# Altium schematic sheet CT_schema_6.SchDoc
size 352 x 211 mm
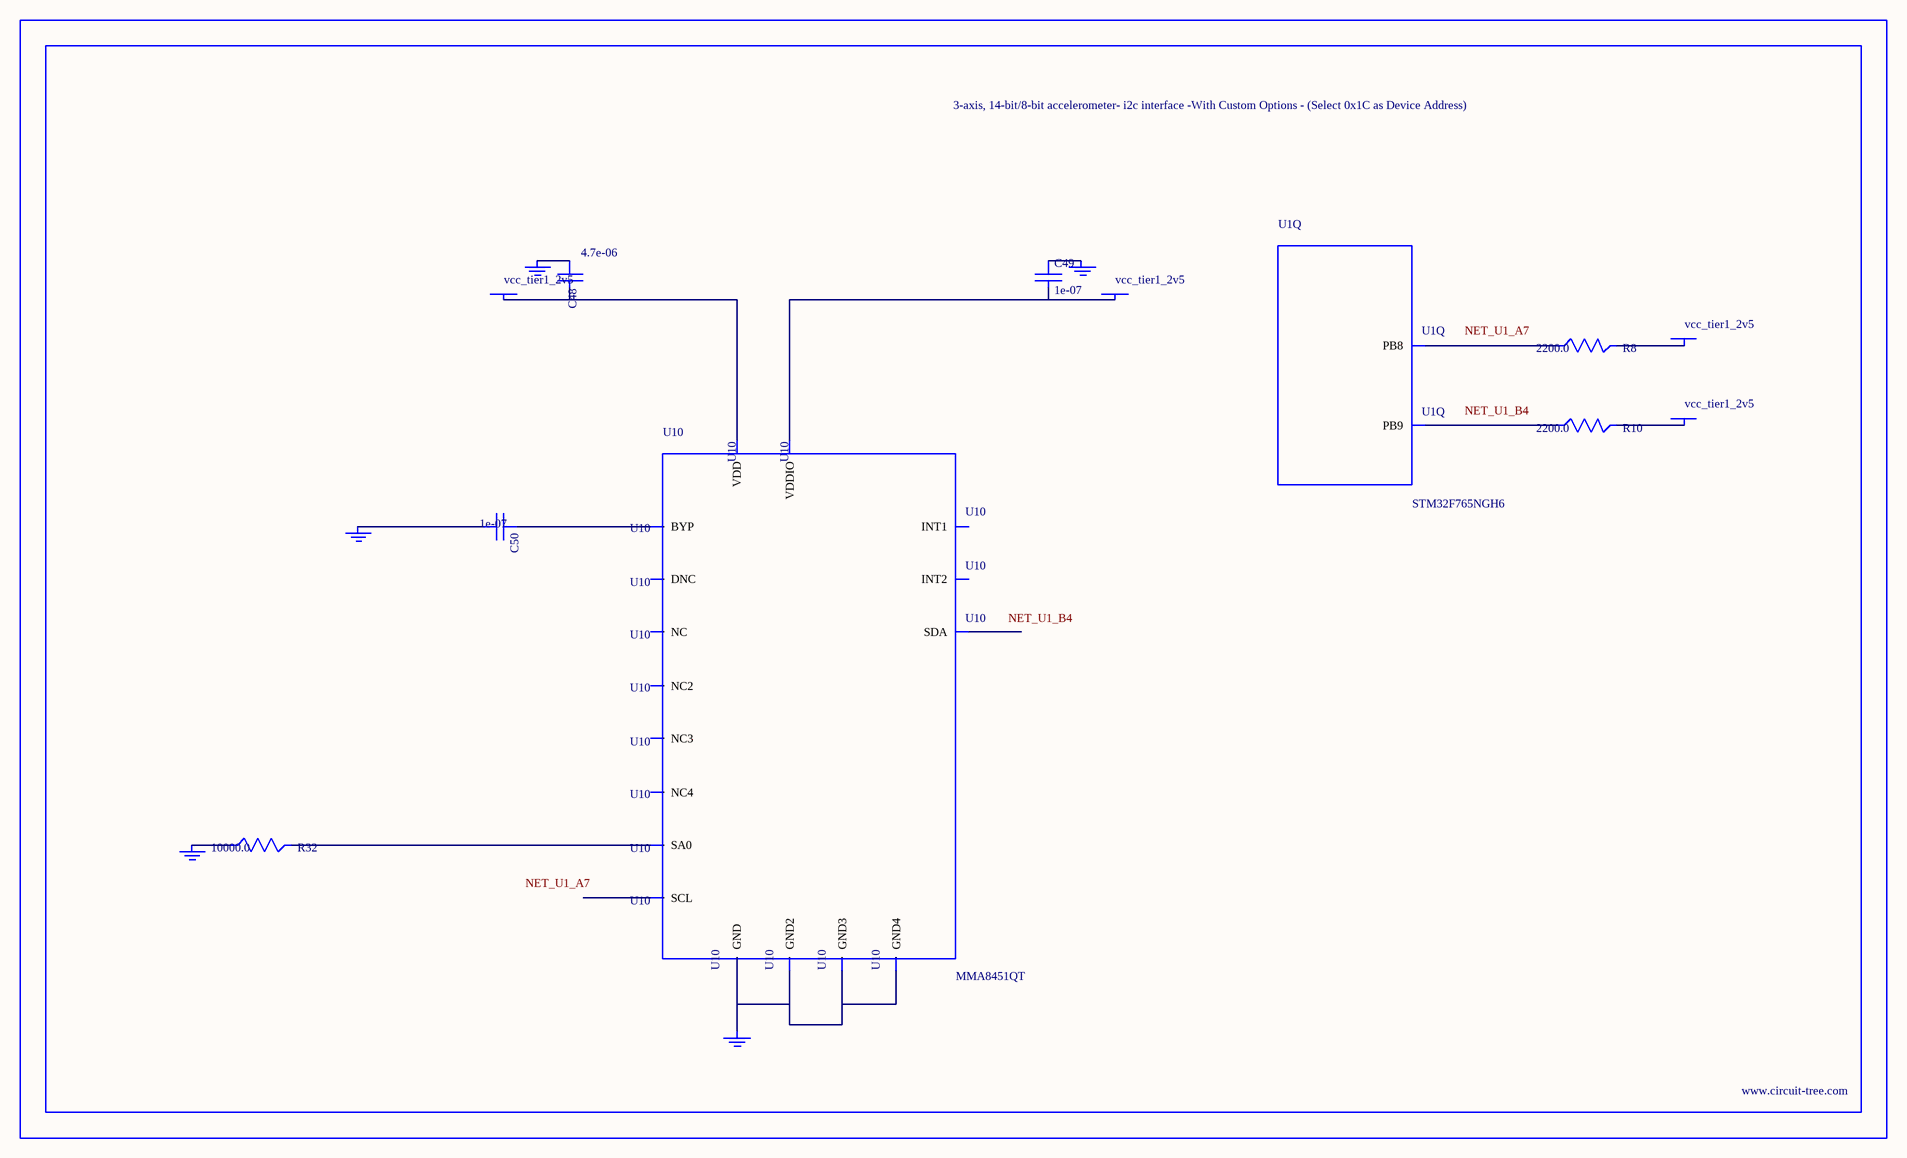
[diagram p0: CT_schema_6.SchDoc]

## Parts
BORDER5  (no value)
C48  4.7e-06  [C0805]
C49  1e-07  [C0402]
C50  1e-07  [C0402]
GND_INSTANCE_5_0  (no value)
GND_INSTANCE_5_1  (no value)
GND_INSTANCE_5_2  (no value)
GND_INSTANCE_5_3  (no value)
GND_INSTANCE_5_4  (no value)
POWER_INSTANCE_5_0  vcc_tier1_2v5
POWER_INSTANCE_5_1  vcc_tier1_2v5
POWER_INSTANCE_5_2  vcc_tier1_2v5
POWER_INSTANCE_5_3  vcc_tier1_2v5
R8  2200.0  [R0603]
R10  2200.0  [R0603]
R32  10000.0  [R0603]
U1  STM32F765NGH6  [TFBGA216]  (part Q of 18)
U10  MMA8451QT  [QFN-16]

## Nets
NetC48_1: C48.1 GND_INSTANCE_5_3.0(GND)
NetC48_2: C48.2 POWER_INSTANCE_5_1.0(PWR) U10.14(VDD)
NetC49_1: C49.1 GND_INSTANCE_5_0.0(GND)
NetC49_2: C49.2 POWER_INSTANCE_5_0.0(PWR) U10.1(VDDIO)
NetC50_1: C50.1 U10.2(BYP)
NetC50_2: C50.2 GND_INSTANCE_5_1.0(GND)
NetGND_INSTANCE_5_2_0: GND_INSTANCE_5_2.0(GND) R32.1
NetGND_INSTANCE_5_4_0: GND_INSTANCE_5_4.0(GND) U10.5(GND) U10.10(GND2) U10.12(GND3) U10.17(GND4)
NetPOWER_INSTANCE_5_2_0: POWER_INSTANCE_5_2.0(PWR) R8.2
NetPOWER_INSTANCE_5_3_0: POWER_INSTANCE_5_3.0(PWR) R10.2
NetR8_1: R8.1 U1.A7(PB8)
NetR10_1: R10.1 U1.B4(PB9)
NetR32_2: R32.2 U10.7(SA0)

Not connected (* = marked no-connect by the designer): U10 3(DNC) 4(SCL) 6(SDA) 8(NC) 9(INT2) 11(INT1) 13(NC2) 15(NC3) 16(NC4)

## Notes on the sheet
- Labels drawn without touching a wire or pin: NET_U1_A7, NET_U1_B4

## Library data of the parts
BORDER5 = BORDER_PAGE5
C48 = C0805C475K4RACTU
C49 C50 = C0402C104K3RACTU
GND_INSTANCE_5_0-GND_INSTANCE_5_4 = GND
POWER_INSTANCE_5_0-POWER_INSTANCE_5_3 = PWR
R8 R10 = RC0603JR-072K2L
R32 = RC0603JR-0710KL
